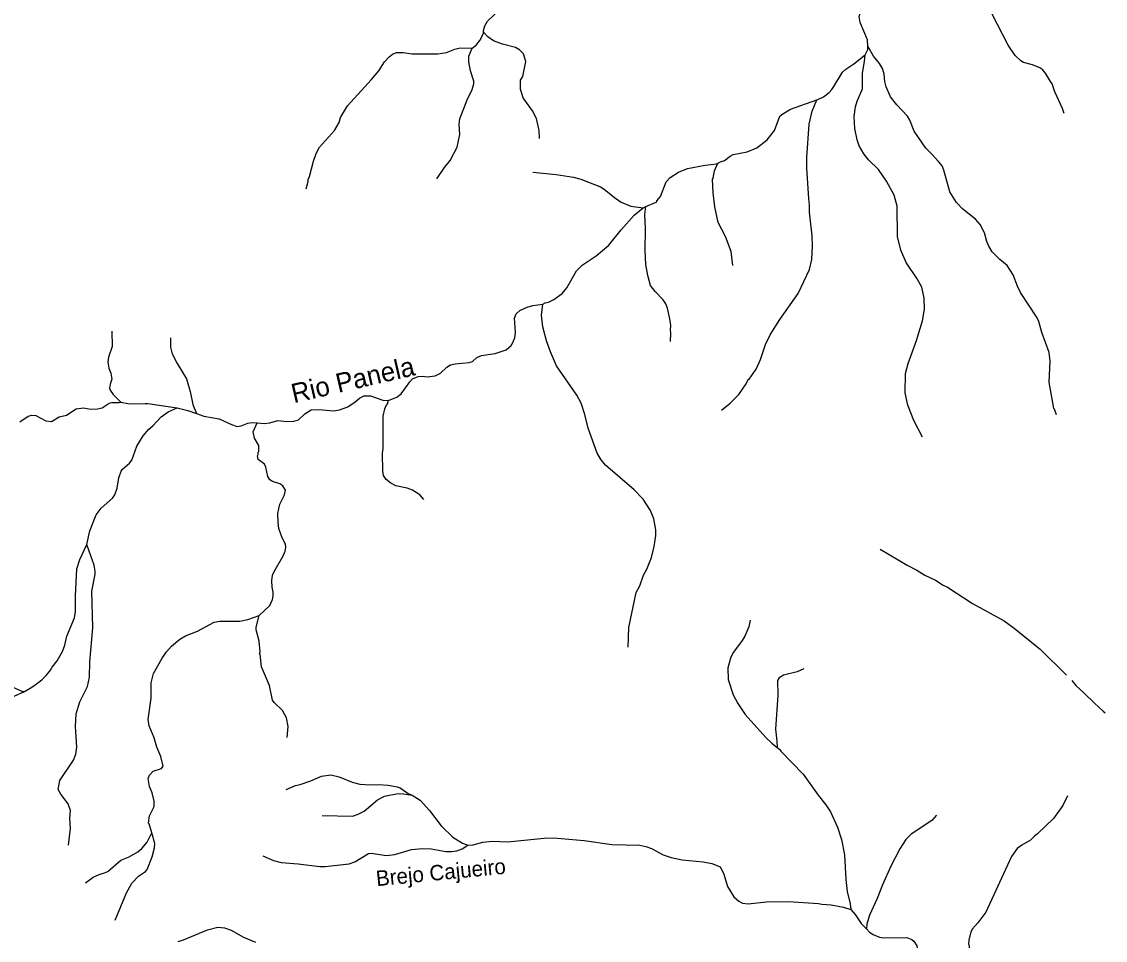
# Model space of a CAD drawing. Extents: x 280.4 to 335.6, y 8893.9 to 8949.5.
# Drawn here: x 324.16 to 335.45, y 8923.61 to 8933.17 of the extents above; entities that cross this region are included whole.
import ezdxf
from ezdxf.enums import TextEntityAlignment as Align

# ---------------------------------------------------------------- set-up
doc = ezdxf.new("R2010")
doc.units = 0
doc.header["$LTSCALE"] = 0.064
doc.linetypes.add('LONG_DASHED', pattern=[7.5, 6, -1.5])
doc.layers.add('61', color=7, linetype='Continuous')
doc.layers.add('7', color=7, linetype='Continuous', lineweight=25)
doc.layers.add('9', color=7, linetype='LONG_DASHED', lineweight=25)

msp = doc.modelspace()

# ---------------------------------------------------------------- linework, layer by layer
at = {"layer": '7'}
msp.add_line((330.634, 8931.2309), (330.6635, 8931.2442), dxfattribs=at)
for points in [[(332.973, 8932.9142), (332.9718, 8932.9793), (332.8936, 8933.1591), (332.8837, 8933.2238), (332.9062, 8933.294), (332.9744, 8933.398), (332.9717, 8933.4277), (332.9352, 8933.4887), (332.8705, 8933.5426), (332.8464, 8933.5711), (332.8344, 8933.6141), (332.8392, 8933.6526)], [(328.9721, 8933.0589), (328.9716, 8933.0781), (328.9867, 8933.1252), (329.0151, 8933.1726), (329.1521, 8933.3059)], [(335.0174, 8932.2127), (334.9999, 8932.2658), (334.9196, 8932.4403), (334.8916, 8932.5228), (334.8766, 8932.5474), (334.8247, 8932.6327), (334.804, 8932.6567), (334.795, 8932.6671), (334.7653, 8932.6898), (334.6878, 8932.7204), (334.594, 8932.7454), (334.5652, 8932.76), (334.5089, 8932.8164), (334.4339, 8932.9251), (334.2666, 8933.2469)], [(328.8557, 8932.8917), (328.8951, 8932.9249), (328.9354, 8932.972), (328.9724, 8933.0468), (328.9721, 8933.0589)], [(329.554, 8931.9532), (329.5506, 8932.0371), (329.5231, 8932.1601), (329.4827, 8932.24), (329.3864, 8932.3757), (329.3579, 8932.4667), (329.3592, 8932.5604), (329.3829, 8932.5994), (329.4147, 8932.7535), (329.3895, 8932.833), (329.3466, 8932.8747), (329.3042, 8932.8986), (329.171, 8932.933), (329.0759, 8932.9696), (329.0183, 8933.0096), (328.9721, 8933.0589)], [(327.125, 8931.4306), (327.1467, 8931.5053), (327.1457, 8931.5254), (327.1594, 8931.5561), (327.202, 8931.7186), (327.2303, 8931.7973), (327.2656, 8931.8611), (327.4212, 8932.0351), (327.4704, 8932.1194), (327.485, 8932.172), (327.5566, 8932.2914), (327.805, 8932.5658), (327.8816, 8932.6584), (327.9422, 8932.7496), (327.991, 8932.8027), (328.0258, 8932.8291), (328.0667, 8932.8463), (328.1361, 8932.8495), (328.229, 8932.8337), (328.4977, 8932.8337), (328.5857, 8932.8495), (328.6728, 8932.8832), (328.7288, 8932.8958), (328.8557, 8932.8917)], [(328.4883, 8931.5331), (328.5657, 8931.6501), (328.6252, 8931.7228), (328.699, 8931.8637), (328.7254, 8931.9956), (328.7208, 8932.1026), (328.7274, 8932.1563), (328.8008, 8932.357), (328.8529, 8932.4612), (328.8711, 8932.5208), (328.8709, 8932.5504), (328.8382, 8932.6579), (328.8184, 8932.7511), (328.8202, 8932.8087), (328.8557, 8932.8917)], [(332.9446, 8932.8252), (332.9736, 8932.8793), (332.973, 8932.9142)], [(334.9379, 8929.0785), (334.9183, 8929.1349), (334.9111, 8929.1416), (334.8623, 8929.4161), (334.8716, 8929.634), (334.8599, 8929.725), (334.7856, 8929.9343), (334.7532, 8930.0477), (334.7351, 8930.0873), (334.564, 8930.3504), (334.5307, 8930.4147), (334.486, 8930.5338), (334.4224, 8930.6328), (334.348, 8930.6944), (334.2692, 8930.7749), (334.2332, 8930.8324), (334.2125, 8930.88), (334.187, 8930.972), (334.1418, 8931.0574), (334.0939, 8931.1134), (333.9632, 8931.2184), (333.8961, 8931.2856), (333.8271, 8931.3982), (333.765, 8931.6239), (333.7475, 8931.6671), (333.7109, 8931.7136), (333.6431, 8931.7856), (333.5789, 8931.8538), (333.4555, 8932.029), (333.4116, 8932.1453), (333.3851, 8932.1862), (333.2759, 8932.3021), (333.21, 8932.3859), (333.1629, 8932.4904), (333.1508, 8932.5464), (333.1442, 8932.6225), (333.1251, 8932.6801), (333.0942, 8932.7349), (333.032, 8932.8086), (332.973, 8932.9142)], [(332.4409, 8932.3549), (332.446, 8932.3567), (332.5136, 8932.3877), (332.5718, 8932.4323), (332.5994, 8932.4617), (332.6187, 8932.4933), (332.711, 8932.6449), (332.7436, 8932.6758), (332.827, 8932.7299), (332.9446, 8932.8252)], [(333.5416, 8928.8441), (333.4508, 8929.0192), (333.3883, 8929.1769), (333.362, 8929.3074), (333.3655, 8929.5074), (333.3918, 8929.6098), (333.4817, 8929.8511), (333.5423, 8930.0567), (333.5633, 8930.1756), (333.5615, 8930.2924), (333.5358, 8930.4066), (333.4869, 8930.4917), (333.3728, 8930.6642), (333.3169, 8930.7905), (333.2819, 8930.9345), (333.2786, 8931.2503), (333.2483, 8931.3648), (333.1687, 8931.5088), (333.0846, 8931.6294), (332.9792, 8931.732), (332.9305, 8931.7935), (332.8833, 8931.8778), (332.8622, 8931.9408), (332.8369, 8932.056), (332.8309, 8932.1811), (332.8457, 8932.2841), (332.8626, 8932.3403), (332.8736, 8932.3665), (332.9174, 8932.4707), (332.9173, 8932.6289), (332.9395, 8932.7561), (332.9446, 8932.8252)], [(331.4114, 8931.696), (331.441, 8931.7115), (331.4807, 8931.7236), (331.5388, 8931.77), (331.5722, 8931.7854), (331.7163, 8931.8138), (331.8196, 8931.8575), (331.9241, 8931.9381), (332.0011, 8932.0364), (332.0573, 8932.1841), (332.087, 8932.2092), (332.1682, 8932.2591), (332.4409, 8932.3549)], [(331.4517, 8929.126), (331.5417, 8929.1986), (331.6323, 8929.2891), (331.7086, 8929.3991), (331.7279, 8929.4446), (331.7365, 8929.4468), (331.8108, 8929.5542), (331.8558, 8929.6525), (331.9067, 8929.8109), (331.9561, 8929.91), (332.0586, 8930.0702), (332.2499, 8930.3413), (332.3676, 8930.5899), (332.3895, 8930.6946), (332.3958, 8930.8353), (332.3926, 8930.9394), (332.3672, 8931.1863), (332.367, 8931.2584), (332.3576, 8931.3271), (332.3368, 8931.6445), (332.3385, 8931.7542), (332.3642, 8932.1018), (332.395, 8932.239), (332.4409, 8932.3549)], [(330.6635, 8931.2442), (330.7763, 8931.2953), (330.7778, 8931.306), (330.8136, 8931.3503), (330.8747, 8931.5024), (330.9144, 8931.5473), (331.0024, 8931.6017), (331.0979, 8931.6396), (331.2789, 8931.6756), (331.3966, 8931.6882), (331.4114, 8931.696)], [(331.5693, 8930.631), (331.5512, 8930.7767), (331.4923, 8930.9337), (331.4156, 8931.0778), (331.3821, 8931.2432), (331.3628, 8931.3872), (331.3566, 8931.531), (331.3631, 8931.5389), (331.3757, 8931.6181), (331.4114, 8931.696)], [(329.4852, 8931.6033), (329.7277, 8931.5799), (329.9085, 8931.5518), (329.9855, 8931.5298), (330.0656, 8931.4987), (330.1905, 8931.4501), (330.2294, 8931.4274), (330.3375, 8931.3374), (330.4064, 8931.2905), (330.505, 8931.2489), (330.634, 8931.2309)], [(329.5893, 8930.2303), (329.6152, 8930.2445), (329.6498, 8930.2484), (329.7032, 8930.2772), (329.7918, 8930.3415), (329.8411, 8930.3995), (329.9395, 8930.5754), (330.0011, 8930.6336), (330.1447, 8930.7327), (330.2773, 8930.8431), (330.406, 8931.0022), (330.5411, 8931.1563), (330.634, 8931.2309)], [(330.92, 8929.8412), (330.9244, 8929.9263), (330.9199, 8929.9629), (330.9213, 8930.0054), (330.913, 8930.0748), (330.8891, 8930.1859), (330.8699, 8930.2307), (330.8414, 8930.2748), (330.761, 8930.3601), (330.7123, 8930.423), (330.6816, 8930.5268), (330.6623, 8930.6427), (330.6559, 8930.7865), (330.659, 8931.0176), (330.6528, 8931.1624), (330.6635, 8931.2442)], [(327.9804, 8929.2269), (328.0706, 8929.2609), (328.1156, 8929.2942), (328.2043, 8929.4207), (328.2347, 8929.4533), (328.2937, 8929.4753), (328.3371, 8929.4783), (328.3864, 8929.4721), (328.4698, 8929.4843), (328.5256, 8929.512), (328.5913, 8929.5743), (328.6272, 8929.5976), (328.6767, 8929.6096), (328.8242, 8929.6203), (328.8588, 8929.6315), (328.9016, 8929.6733), (328.9509, 8929.6958), (329.0923, 8929.7144), (329.2075, 8929.7553), (329.2597, 8929.7988), (329.276, 8929.8215), (329.2992, 8929.8799), (329.3045, 8929.9389), (329.295, 8930.0835), (329.311, 8930.1277), (329.3491, 8930.162), (329.4283, 8930.1983), (329.4852, 8930.214), (329.5893, 8930.2303)], [(330.4796, 8926.66), (330.4864, 8926.8638), (330.5618, 8927.2266), (330.5992, 8927.299), (330.6378, 8927.4074), (330.6737, 8927.4704), (330.7219, 8927.5928), (330.7501, 8927.7057), (330.7662, 8927.8215), (330.7678, 8927.8807), (330.7472, 8927.9935), (330.712, 8928.0832), (330.6343, 8928.1988), (330.5413, 8928.296), (330.2433, 8928.5525), (330.1987, 8928.6075), (330.1542, 8928.6781), (330.0612, 8928.9371), (330.0275, 8929.081), (329.9886, 8929.1976), (329.943, 8929.2826), (329.7325, 8929.5887), (329.6691, 8929.7342), (329.6294, 8929.8487), (329.5909, 8929.9926), (329.5747, 8930.115), (329.5893, 8930.2303)], [(325.1049, 8929.9484), (325.105, 8929.79), (325.0697, 8929.6766), (325.0617, 8929.627), (325.071, 8929.5629), (325.0939, 8929.5122), (325.1016, 8929.4472), (325.0842, 8929.3953), (325.0806, 8929.3557), (325.087, 8929.3332), (325.1168, 8929.2892), (325.1975, 8929.2075)], [(325.7145, 8929.8777), (325.7142, 8929.7797), (325.7322, 8929.7104), (325.782, 8929.6098), (325.8802, 8929.4533), (325.9188, 8929.3184), (325.9448, 8929.1835), (325.9848, 8929.0902)], [(326.7473, 8928.9939), (326.8329, 8929.0192), (326.924, 8929.0083), (326.9966, 8929.0113), (327.0453, 8929.0262), (327.1118, 8929.086), (327.1792, 8929.1296), (327.2574, 8929.1329), (327.411, 8929.1186), (327.4749, 8929.1287), (327.5603, 8929.1606), (327.6374, 8929.2125), (327.6823, 8929.2523), (327.7254, 8929.2733), (327.7972, 8929.2734), (327.9227, 8929.2309), (327.9804, 8929.2269)], [(324.145, 8929.0051), (324.2318, 8929.0633), (324.2699, 8929.0733), (324.3108, 8929.0686), (324.4156, 8929.0147), (324.4762, 8929.0069), (324.5539, 8929.0547), (324.6313, 8929.073), (324.7333, 8929.1394), (324.8083, 8929.1488), (324.8833, 8929.1362), (324.9529, 8929.1394), (325.0041, 8929.1508), (325.0665, 8929.1927), (325.0846, 8929.201), (325.1033, 8929.2048), (325.164, 8929.2067), (325.1804, 8929.2058), (325.1975, 8929.2075)], [(325.1975, 8929.2075), (325.2703, 8929.1938), (325.2935, 8929.1933), (325.4497, 8929.1953), (325.4774, 8929.1952), (325.7818, 8929.1515)], [(328.3525, 8928.196), (328.3097, 8928.2452), (328.2333, 8928.2923), (328.1764, 8928.3127), (328.0613, 8928.34), (328.0066, 8928.3649), (327.9575, 8928.4057), (327.9319, 8928.4454), (327.9244, 8928.49), (327.9211, 8928.6766), (327.9276, 8928.7284), (327.9276, 8929.0619), (327.9446, 8929.1395), (327.9581, 8929.1727), (327.9769, 8929.1955), (327.9804, 8929.2269)], [(324.8412, 8927.7267), (324.8731, 8927.8688), (324.9414, 8928.0351), (324.9909, 8928.1056), (325.1092, 8928.2099), (325.1347, 8928.243), (325.1604, 8928.3125), (325.1755, 8928.4203), (325.199, 8928.4893), (325.2158, 8928.513), (325.2875, 8928.5753), (325.3119, 8928.6065), (325.364, 8928.7523), (325.4296, 8928.8578), (325.4887, 8928.9298), (325.5283, 8928.9631), (325.6181, 8929.0573), (325.688, 8929.1069), (325.7818, 8929.1515)], [(325.7818, 8929.1515), (325.8941, 8929.1224), (325.9848, 8929.0902)], [(325.9848, 8929.0902), (326.0622, 8929.0627), (326.2194, 8929.0359), (326.3482, 8928.9772), (326.409, 8928.9572), (326.4497, 8928.9611), (326.5187, 8928.9889), (326.5651, 8928.9985), (326.6162, 8928.9933)], [(326.6386, 8926.9885), (326.7488, 8927.0924), (326.7742, 8927.1555), (326.7842, 8927.1926), (326.7825, 8927.232), (326.7712, 8927.285), (326.7697, 8927.3489), (326.7723, 8927.383), (326.7809, 8927.419), (326.8035, 8927.4633), (326.8829, 8927.6034), (326.9062, 8927.6597), (326.9135, 8927.7), (326.9101, 8927.7325), (326.8778, 8927.7975), (326.8429, 8927.8935), (326.8337, 8927.9551), (326.8321, 8928.0502), (326.8516, 8928.1485), (326.9007, 8928.2438), (326.9118, 8928.2949), (326.8831, 8928.3396), (326.8527, 8928.3595), (326.7768, 8928.3826), (326.7469, 8928.4015), (326.7264, 8928.4364), (326.7074, 8928.5309), (326.6926, 8928.5641), (326.6255, 8928.6118), (326.6194, 8928.652), (326.6255, 8928.6628), (326.6259, 8928.6891), (326.6321, 8928.6944), (326.6335, 8928.7586), (326.5873, 8928.833), (326.5761, 8928.8992), (326.6162, 8928.9933)], [(326.6162, 8928.9933), (326.6882, 8928.986), (326.7473, 8928.9939)], [(324.1923, 8926.1967), (324.269, 8926.2425), (324.3061, 8926.2665), (324.3746, 8926.3203), (324.4208, 8926.3636), (324.4646, 8926.42), (324.4812, 8926.4525), (324.5327, 8926.5172), (324.588, 8926.6153), (324.6147, 8926.6793), (324.6363, 8926.7724), (324.713, 8926.9644), (324.7258, 8927.0291), (324.7244, 8927.189), (324.7401, 8927.4754), (324.7688, 8927.5713), (324.8412, 8927.7267)], [(324.6529, 8924.6), (324.6714, 8924.7734), (324.665, 8924.8781), (324.6729, 8924.9598), (324.6477, 8925.0286), (324.5715, 8925.1279), (324.5439, 8925.1787), (324.5601, 8925.2711), (324.7046, 8925.4828), (324.7274, 8925.5474), (324.7371, 8925.6184), (324.7259, 8925.8336), (324.7324, 8925.9639), (324.7688, 8926.0904), (324.8505, 8926.2511), (324.8697, 8926.347), (324.873, 8926.5077), (324.9049, 8926.8595), (324.8954, 8927.2426), (324.9302, 8927.4202), (324.9305, 8927.4504), (324.9179, 8927.5137), (324.8665, 8927.6576), (324.8412, 8927.7267)], [(325.5186, 8924.7267), (325.4918, 8924.8222), (325.4856, 8924.8288), (325.4939, 8924.905), (325.5444, 8925.0029), (325.5446, 8925.0573), (325.5238, 8925.1443), (325.4963, 8925.2099), (325.4809, 8925.2932), (325.4956, 8925.3287), (325.5319, 8925.369), (325.6214, 8925.3965), (325.6375, 8925.4211), (325.6148, 8925.5225), (325.5732, 8925.6185), (325.5424, 8925.7153), (325.4925, 8925.8401), (325.4807, 8925.9056), (325.5126, 8926.1303), (325.5139, 8926.2865), (325.5375, 8926.3869), (325.6275, 8926.5447), (325.6711, 8926.6093), (325.725, 8926.6713), (325.8095, 8926.7432), (325.871, 8926.7756), (325.995, 8926.8249), (326.1684, 8926.9195), (326.2259, 8926.9291), (326.4354, 8926.931), (326.5195, 8926.9466), (326.6386, 8926.9885)], [(326.9287, 8925.7186), (326.9393, 8925.8353), (326.9205, 8925.9235), (326.8811, 8926.002), (326.7926, 8926.0827), (326.7762, 8926.1063), (326.7437, 8926.2588), (326.6608, 8926.4564), (326.6481, 8926.5855), (326.6418, 8926.5915), (326.6464, 8926.6108), (326.6386, 8926.723), (326.6067, 8926.839), (326.6069, 8926.8692), (326.6386, 8926.9885)], [(331.7486, 8926.94), (331.7336, 8926.8718), (331.6925, 8926.7731), (331.6661, 8926.7271), (331.5762, 8926.6063), (331.5476, 8926.5567), (331.5148, 8926.4454), (331.5211, 8926.3246), (331.5733, 8926.1618), (331.6193, 8926.0737), (331.6966, 8925.959), (331.9119, 8925.718), (331.9727, 8925.6588), (332.0285, 8925.6165)], [(332.3081, 8926.4345), (332.2378, 8926.4026), (332.0959, 8926.3664), (332.0505, 8926.3406), (332.0315, 8926.3116), (332.036, 8926.1584), (332.0136, 8925.8052), (332.0279, 8925.6825), (332.0285, 8925.6165)], [(323.995, 8926.2787), (324.1664, 8926.2014), (324.1923, 8926.1967)], [(323.4272, 8924.7691), (323.4225, 8924.788), (323.3855, 8924.8457), (323.3665, 8924.8917), (323.3394, 8925.0509), (323.2975, 8925.1492), (323.2867, 8925.2108), (323.2865, 8925.2652), (323.2993, 8925.3707), (323.2675, 8925.5314), (323.2755, 8925.5679), (323.3373, 8925.6907), (323.3868, 8925.7566), (323.4422, 8925.8085), (323.5407, 8925.8801), (323.6176, 8925.9599), (323.656, 8925.9791), (323.7391, 8925.9963), (323.7848, 8926.0142), (323.8559, 8926.0815), (323.9374, 8926.1218), (324.0879, 8926.1489), (324.1923, 8926.1967)], [(332.0285, 8925.6165), (332.059, 8925.5934), (332.0675, 8925.5766), (332.2998, 8925.3379), (332.455, 8925.1189), (332.5371, 8925.019), (332.585, 8924.9453), (332.6572, 8924.7845), (332.7011, 8924.6589), (332.7319, 8924.4966), (332.7446, 8924.2417), (332.7573, 8924.1152), (332.7907, 8923.9872), (332.7972, 8923.9277)], [(326.9186, 8925.178), (327.0153, 8925.2209), (327.0639, 8925.2308), (327.1765, 8925.2679), (327.2865, 8925.3182), (327.3838, 8925.3298), (327.4707, 8925.3089), (327.604, 8925.2559), (327.6848, 8925.2342), (327.7947, 8925.2253), (327.8793, 8925.2292), (327.9787, 8925.2243), (328.0753, 8925.2064), (328.1066, 8925.1938), (328.1881, 8925.1354), (328.2302, 8925.1179)], [(327.2922, 8924.909), (327.6077, 8924.9014), (327.6679, 8924.92), (327.7309, 8924.953), (327.8694, 8925.072), (327.9429, 8925.1105), (328.0826, 8925.1363), (328.1411, 8925.1347), (328.2302, 8925.1179)], [(328.2302, 8925.1179), (328.3118, 8925.067), (328.4105, 8924.9588), (328.5332, 8924.8011), (328.6515, 8924.6805), (328.753, 8924.6198), (328.8098, 8924.6002)], [(335.0527, 8925.1116), (335.0042, 8925.0102), (334.9064, 8924.877), (334.7409, 8924.7162), (334.711, 8924.6975), (334.6656, 8924.6523), (334.5782, 8924.6002), (334.5283, 8924.5627), (334.4678, 8924.4805), (334.2011, 8923.9027), (334.1203, 8923.7904), (334.064, 8923.7274), (334.0475, 8923.6974), (334.0239, 8923.6116), (334.0209, 8923.5682), (334.0272, 8923.5531), (334.0287, 8923.4972), (334.0129, 8923.4115), (333.9887, 8923.3533), (333.9484, 8923.295), (333.911, 8923.231), (333.9026, 8923.2073), (333.911, 8923.1197)], [(333.6889, 8924.9109), (333.6402, 8924.8571), (333.4253, 8924.7121), (333.3688, 8924.6587), (333.3075, 8924.559), (333.2144, 8924.3793), (333.1258, 8924.1863), (333.0697, 8924.0423), (332.9893, 8923.8714), (332.9621, 8923.7753), (332.958, 8923.7282)], [(324.8293, 8924.2057), (324.9072, 8924.2649), (324.9699, 8924.2948), (325.0271, 8924.3098), (325.06, 8924.3256), (325.1955, 8924.4414), (325.2849, 8924.4788), (325.3737, 8924.5284), (325.4155, 8924.5627), (325.4722, 8924.6305), (325.5186, 8924.7267)], [(325.1364, 8923.8176), (325.2553, 8924.1016), (325.3117, 8924.2045), (325.3798, 8924.2772), (325.455, 8924.324), (325.4721, 8924.3456), (325.522, 8924.4784), (325.5477, 8924.5719), (325.5492, 8924.6176), (325.5186, 8924.7267)], [(328.8098, 8924.6002), (328.8651, 8924.603), (328.9642, 8924.6305), (329.0623, 8924.6421), (329.2237, 8924.6327), (329.6051, 8924.6726), (329.702, 8924.6742), (330.0218, 8924.6487), (330.3097, 8924.6071), (330.6012, 8924.6001), (330.6623, 8924.5862), (330.7223, 8924.5625), (330.8424, 8924.4995), (330.9253, 8924.4694), (331.039, 8924.4473), (331.2589, 8924.4245), (331.3503, 8924.4064), (331.4287, 8924.3771), (331.4462, 8924.3568), (331.4747, 8924.2967), (331.5129, 8924.1695), (331.5769, 8924.0604), (331.6308, 8924.0174), (331.6685, 8923.9963), (331.7291, 8923.9898), (331.9201, 8924.0089), (332.144, 8924.0121), (332.4614, 8923.9914), (332.4958, 8923.9834), (332.5926, 8923.9766), (332.7189, 8923.9529), (332.7972, 8923.9277)], [(326.6745, 8924.4862), (326.7856, 8924.4392), (326.8658, 8924.4177), (327.0447, 8924.4055), (327.2686, 8924.3768), (327.323, 8924.3768), (327.5741, 8924.4029), (327.6315, 8924.4271), (327.7766, 8924.5122), (327.8033, 8924.517), (327.9624, 8924.4921), (328.0491, 8924.5031), (328.2218, 8924.5526), (328.3369, 8924.5638), (328.4282, 8924.5604), (328.58, 8924.5335), (328.6383, 8924.5335), (328.6952, 8924.5415), (328.7512, 8924.5601), (328.8098, 8924.6002)], [(332.7972, 8923.9277), (332.8434, 8923.879), (332.9045, 8923.7819), (332.958, 8923.7282)], [(325.7941, 8923.5949), (325.8491, 8923.6125), (326.0975, 8923.7192), (326.2076, 8923.7449), (326.2769, 8923.7393), (326.3449, 8923.7159), (326.4729, 8923.6424), (326.6001, 8923.5899)], [(332.958, 8923.7282), (332.9915, 8923.6945), (333.0299, 8923.6679), (333.0946, 8923.6425), (333.1377, 8923.6343), (333.3793, 8923.6363), (333.4306, 8923.6184), (333.4518, 8923.6004), (333.4848, 8923.5498), (333.5156, 8923.3813), (333.5419, 8923.3191), (333.5736, 8923.2681), (333.5953, 8923.2502), (333.6952, 8923.1961), (333.769, 8923.1659)]]:
    msp.add_lwpolyline(points, dxfattribs=at)
at = {"layer": '9'}
msp.add_lwpolyline([(333.1021, 8927.68), (333.3843, 8927.5113), (333.4823, 8927.4605), (333.5681, 8927.4074), (333.677, 8927.356), (333.7563, 8927.3037), (333.8022, 8927.2822), (334.0629, 8927.1128), (334.3933, 8926.9323), (334.498, 8926.8567), (334.7686, 8926.637), (335.0974, 8926.3112), (335.1399, 8926.2614), (335.2224, 8926.1857), (335.334, 8926.0769), (335.3768, 8926.0362), (335.4227, 8925.9936), (335.446, 8925.9759)], dxfattribs=at)

# ---------------------------------------------------------------- texts
at = {"layer": '61'}
for s, height, rotation, p in [('Rio Panela', 0.2, 12.995, (327.6344, 8929.3448)), ('Brejo Cajueiro', 0.16, 5.528, (328.5356, 8924.2371))]:
    msp.add_text(s, height=height, rotation=rotation, dxfattribs=at).set_placement(p, align=Align.CENTER)

doc.saveas('drawing.dxf')
